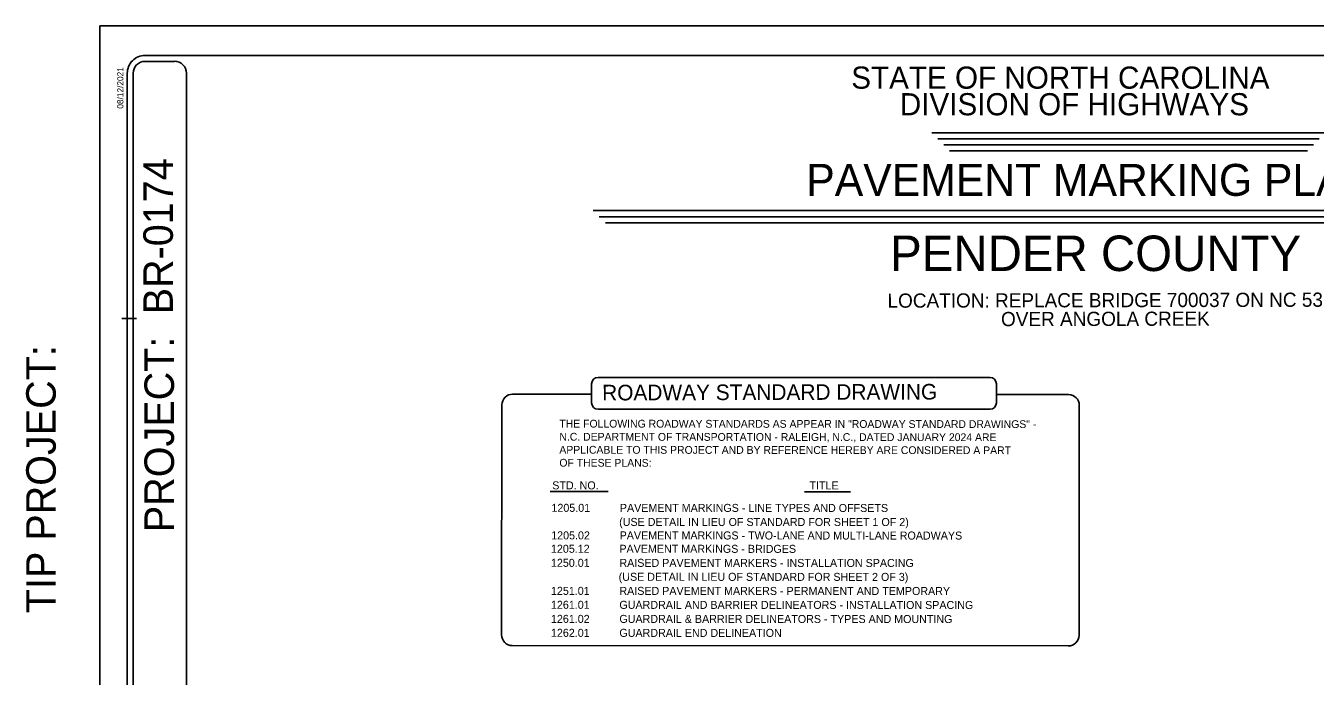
# Model space of a CAD drawing. Extents: x -63 to 3072, y 0 to 1100.
# Drawn here: x -63 to 1028, y 550 to 1100 of the extents above; entities that cross this region are included whole.
import ezdxf

# ---------------------------------------------------------------- set-up
doc = ezdxf.new("R2010")
doc.units = 0
for name, color, linetype in [('Scratch_Level_0', 7, 'Continuous'), ('Sheet Data Field CELL', 7, 'Continuous'), ('Sheet Data Text CELL', 7, 'Continuous'), ('Sheet_Data_Field_CELL', 7, 'Continuous'), ('Sheet_RDY_PE_Seal_Cell', 7, 'Continuous')]:
    doc.layers.add(name, color=color, linetype=linetype)

msp = doc.modelspace()

# ---------------------------------------------------------------- linework, layer by layer
at = {"layer": 'Scratch_Level_0'}
for p, q in [((0, 1100), (1700, 1100)), ((0, 0), (0, 1100))]:
    msp.add_line(p, q, dxfattribs=at)
at = {"layer": 'Sheet_RDY_PE_Seal_Cell'}
for p, q in [((38.1, 1074.9), (1652, 1074.9)), ((23, 1059.9), (23, 40)), ((28.1, 40), (28.1, 1059.9)), ((73.1, 40), (73.1, 1060)), ((703.7, 1009.4), (1036.4, 1009.4)), ((708.7, 1004.4), (1031.4, 1004.4)), ((713.7, 999.4), (1026.4, 999.4)), ((718.7, 994.4), (1021.4, 994.4)), ((417.2, 943.7), (1322.9, 943.7)), ((422.3, 938.5), (1317.7, 938.5)), ((427.5, 933.4), (1312.6, 933.4)), ((18.5, 852.5), (31, 852.5)), ((18.5, 852.5), (31, 852.5)), ((415.8, 781.2), (415.8, 797.2)), ((758.4, 781.2), (758.4, 797.2)), ((349.1, 788.4), (415.9, 788.4)), ((758.4, 788.3), (819.3, 788.2)), ((339.7, 585), (340, 779.4)), ((828.2, 584.7), (828.4, 779.1)), ((380.7, 706.1), (430, 706.1)), ((595.9, 706), (634.8, 706)), ((348.8, 575.9), (819.1, 575.7))]:
    msp.add_line(p, q, dxfattribs=at)
for points in [[(63, 1069.9), (38.1, 1069.9)], [(421.3, 802.7), (752.9, 802.7)], [(421.3, 775.7), (752.9, 775.7)]]:
    msp.add_lwpolyline(points, dxfattribs=at)
for centre, radius, start, end in [((38.1, 1059.9), 15, 89.9714, 180), ((38.1, 1059.9), 10, 89.9714, 180), ((63.1, 1060), 10, 0, 90), ((421.3, 797.2), 5.45, 90, 180), ((752.9, 797.2), 5.45, 0, 90), ((349.1, 779.4), 9.09, 89.9734, 179.9734), ((819.3, 779.1), 9.09, 359.9734, 89.9734), ((421.3, 781.2), 5.45, 180, 270), ((752.9, 781.2), 5.45, 270, 0), ((348.8, 585), 9.09, 179.9734, 269.9734), ((819.1, 584.7), 9.09, 269.9734, 359.9734)]:
    msp.add_arc(centre, radius, start, end, dxfattribs=at)

# ---------------------------------------------------------------- texts
at = {"layer": 'Sheet Data Field CELL'}
msp.add_text('PENDER COUNTY ', height=30, dxfattribs=at).set_placement((668.4, 892.6))
at = {"layer": 'Sheet Data Text CELL'}
for s, height, rotation, p in [('PAVEMENT MARKING PLAN', 26.998, 0, (597.5, 956.2)), ('LOCATION: REPLACE BRIDGE 700037 ON NC 53', 12, 0.1248, (666.2, 861.6)), ('OVER ANGOLA CREEK', 12, 0.1248, (762.2, 846)), ('ROADWAY STANDARD DRAWING', 13.2, 0.1557, (424.8, 783.2))]:
    msp.add_text(s, height=height, rotation=rotation, dxfattribs=at).set_placement(p)
at = {"layer": 'Sheet_Data_Field_CELL'}
for s, height, rotation, p in [('THE FOLLOWING ROADWAY STANDARDS AS APPEAR IN "ROADWAY STANDARD DRAWINGS" - ', 6.6, 359.9332, (388.6, 760.3)), ('N.C. DEPARTMENT OF TRANSPORTATION - RALEIGH, N.C., DATED JANUARY 2024 ARE', 6.6, 359.9332, (388.6, 749.2)), ('APPLICABLE TO THIS PROJECT AND BY REFERENCE HEREBY ARE CONSIDERED A PART', 6.6, 359.9332, (388.6, 738.2)), ('OF THESE PLANS:', 6.6, 359.9332, (388.6, 727.2)), ('STD. NO.', 6.77, 359.9734, (382.6, 708)), ('TITLE', 6.77, 359.9734, (600.2, 707.9)), ('1205.01          PAVEMENT MARKINGS - LINE TYPES AND OFFSETS', 6.771, 359.9734, (381.9, 689)), ('            (USE DETAIL IN LIEU OF STANDARD FOR SHEET 1 OF 2)', 6.771, 359.9734, (409, 677.1)), ('1205.02          PAVEMENT MARKINGS - TWO-LANE AND MULTI-LANE ROADWAYS', 6.771, 359.9734, (381.7, 665.7)), ('1205.12          PAVEMENT MARKINGS - BRIDGES', 6.771, 359.9734, (381.5, 654.4)), ('1250.01          RAISED PAVEMENT MARKERS - INSTALLATION SPACING', 6.771, 359.9734, (381.5, 642.5)), ('            (USE DETAIL IN LIEU OF STANDARD FOR SHEET 2 OF 3)', 6.771, 359.9734, (408.6, 630.7)), ('1251.01          RAISED PAVEMENT MARKERS - PERMANENT AND TEMPORARY', 6.771, 359.9734, (381.5, 618.8)), ('1261.01          GUARDRAIL AND BARRIER DELINEATORS - INSTALLATION SPACING', 6.771, 359.9734, (381.5, 607)), ('1261.02          GUARDRAIL & BARRIER DELINEATORS - TYPES AND MOUNTING', 6.771, 359.9734, (381.5, 595.1)), ('1262.01          GUARDRAIL END DELINEATION', 6.771, 359.9734, (381.5, 583.3))]:
    msp.add_text(s, height=height, rotation=rotation, dxfattribs=at).set_placement(p)
at = {"layer": 'Sheet_RDY_PE_Seal_Cell'}
for s, height, p in [('08/12/2021', 5.25, (19.8, 1029.9)), ('BR-0174', 25, (61.7, 856)), ('PROJECT:', 25, (62.6, 671.8)), ('TIP PROJECT:', 25, (-37.4, 603.3))]:
    msp.add_text(s, height=height, rotation=90, dxfattribs=at).set_placement(p)
for s, p in [('STATE OF NORTH CAROLINA', (635.5, 1046.8)), ('DIVISION OF HIGHWAYS', (676.6, 1024.3))]:
    msp.add_text(s, height=18.75, dxfattribs=at).set_placement(p)

doc.saveas('drawing.dxf')
